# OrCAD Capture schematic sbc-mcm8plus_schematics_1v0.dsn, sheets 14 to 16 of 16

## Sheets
14 14. UARTs, uSD, FlexSPI, etc.: size A2; title: SBC-MCM8PLUS   14. UARTs, uSD, FlexSPI, etc.
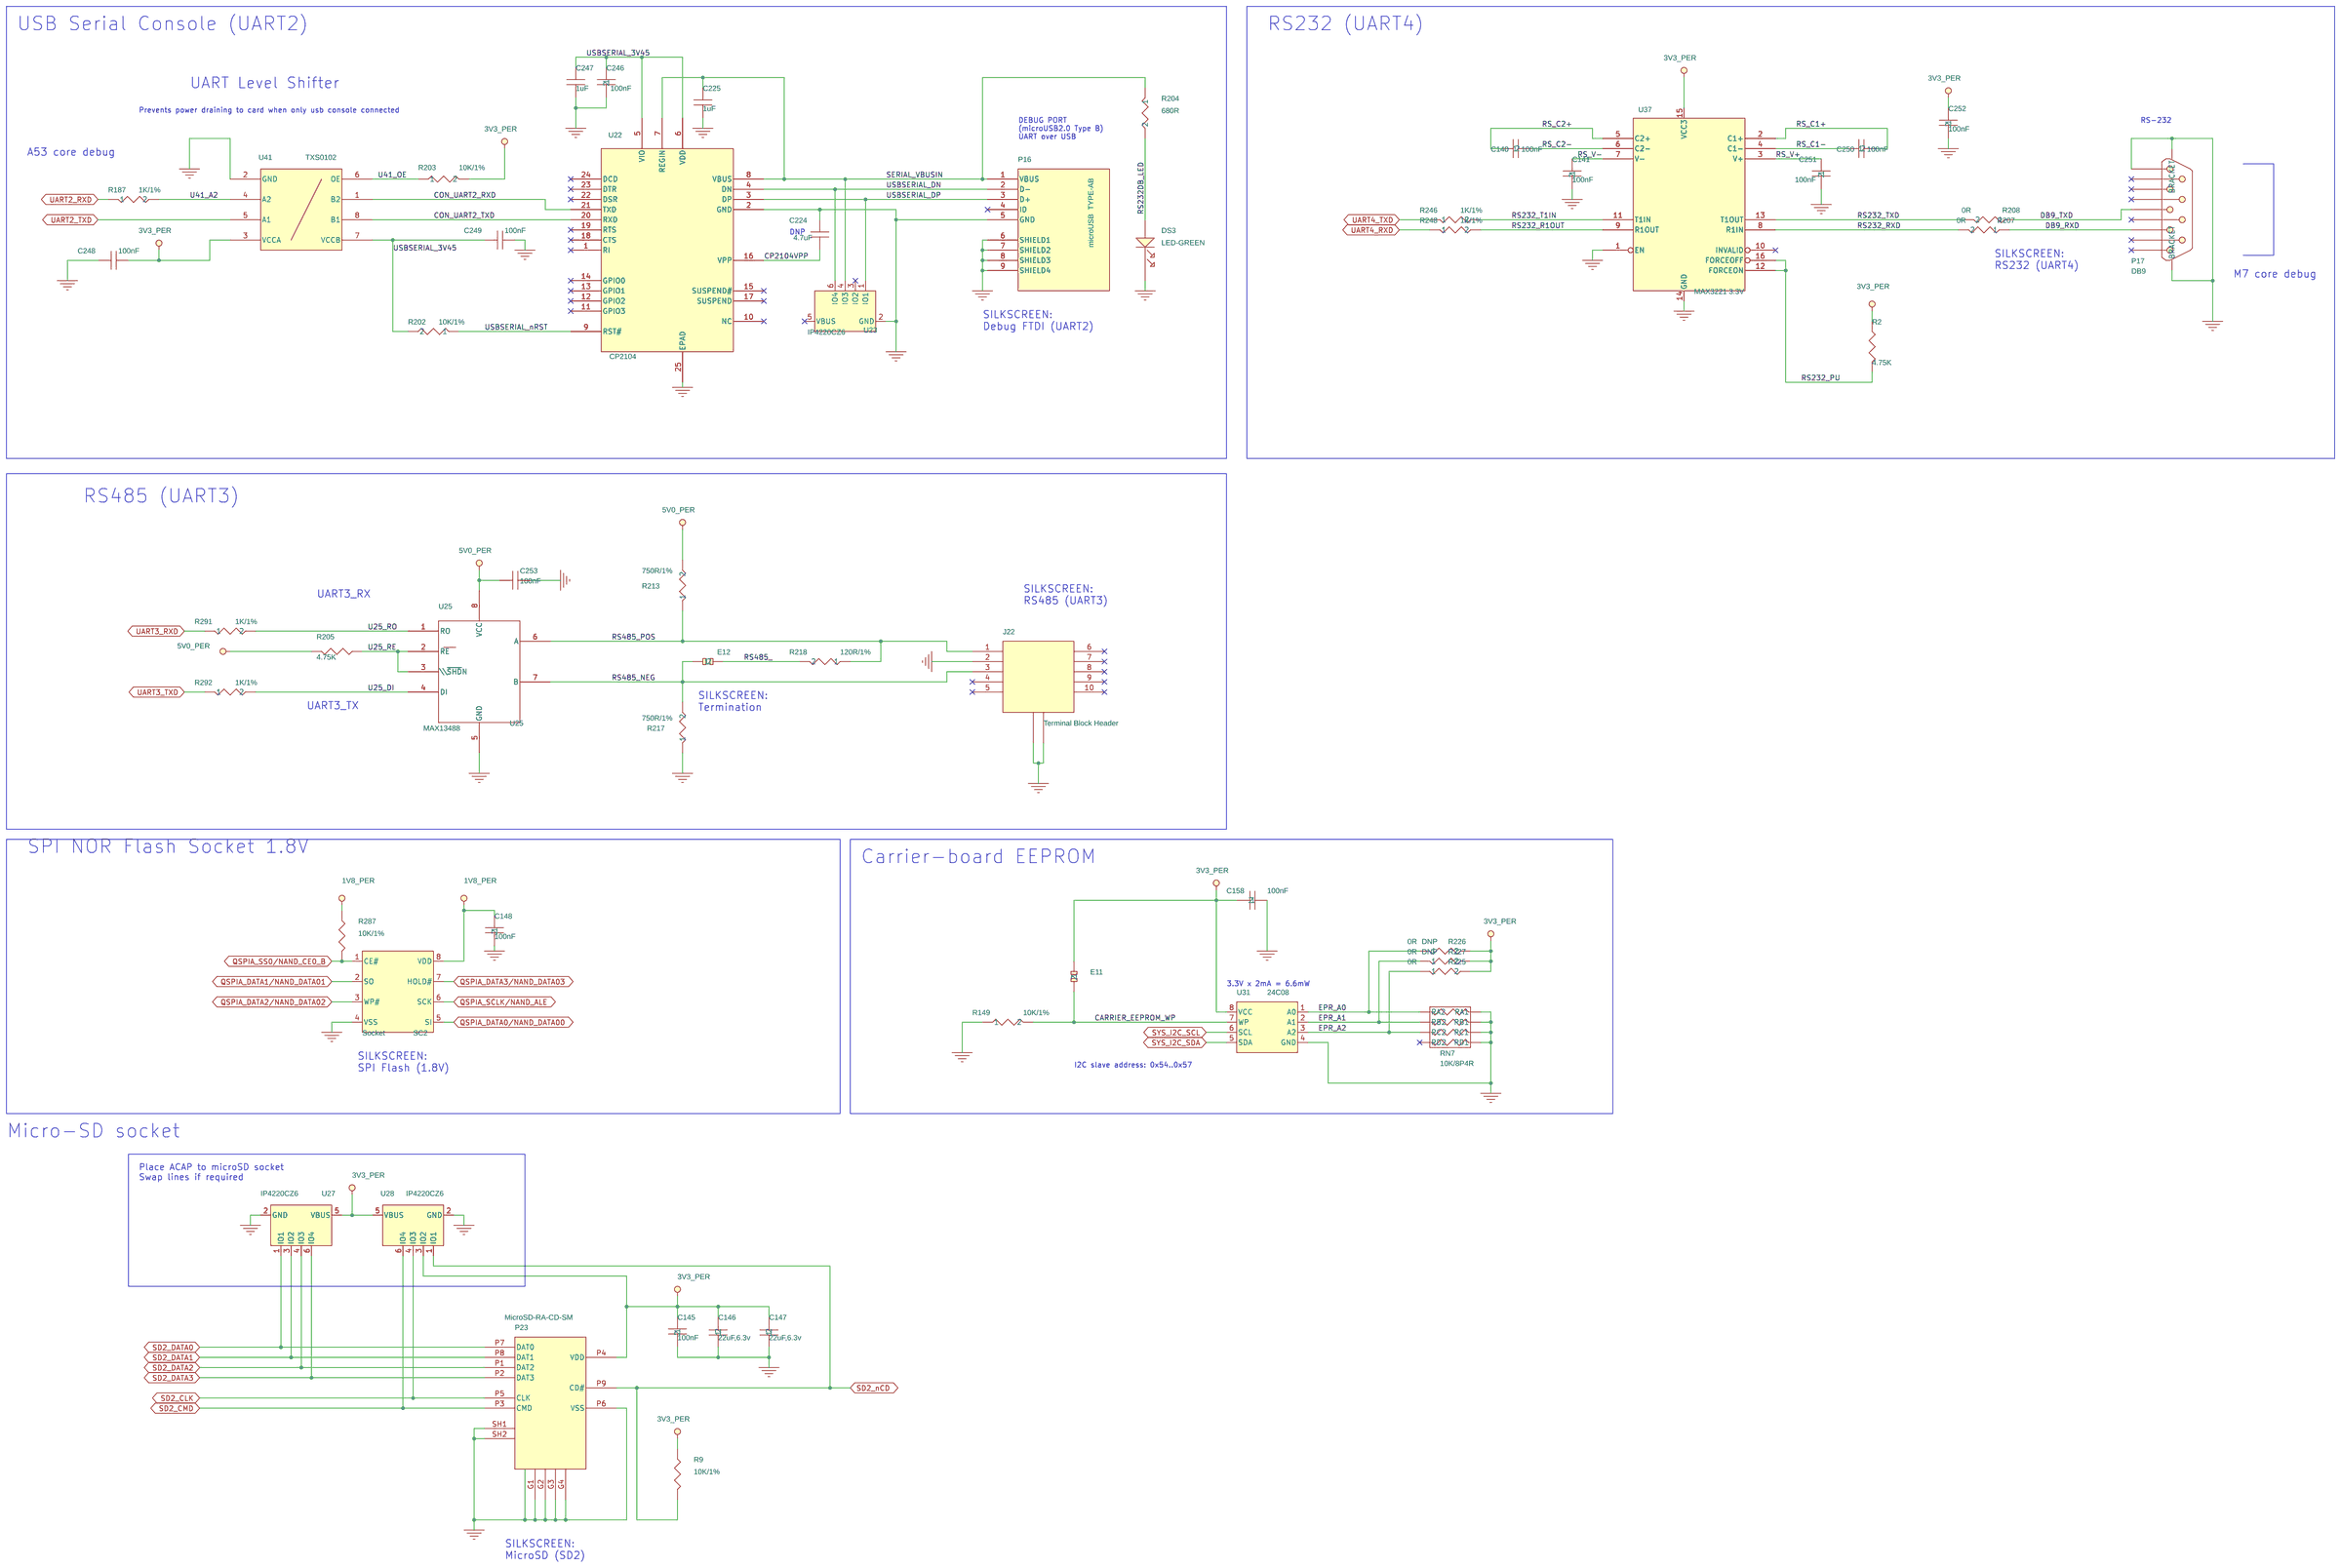
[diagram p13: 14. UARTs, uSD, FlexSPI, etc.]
15 15. WiFi + BT on SDHC1: size A3; title: SBC-MCM8PLUS   15. WiFi + BT on SDHC1
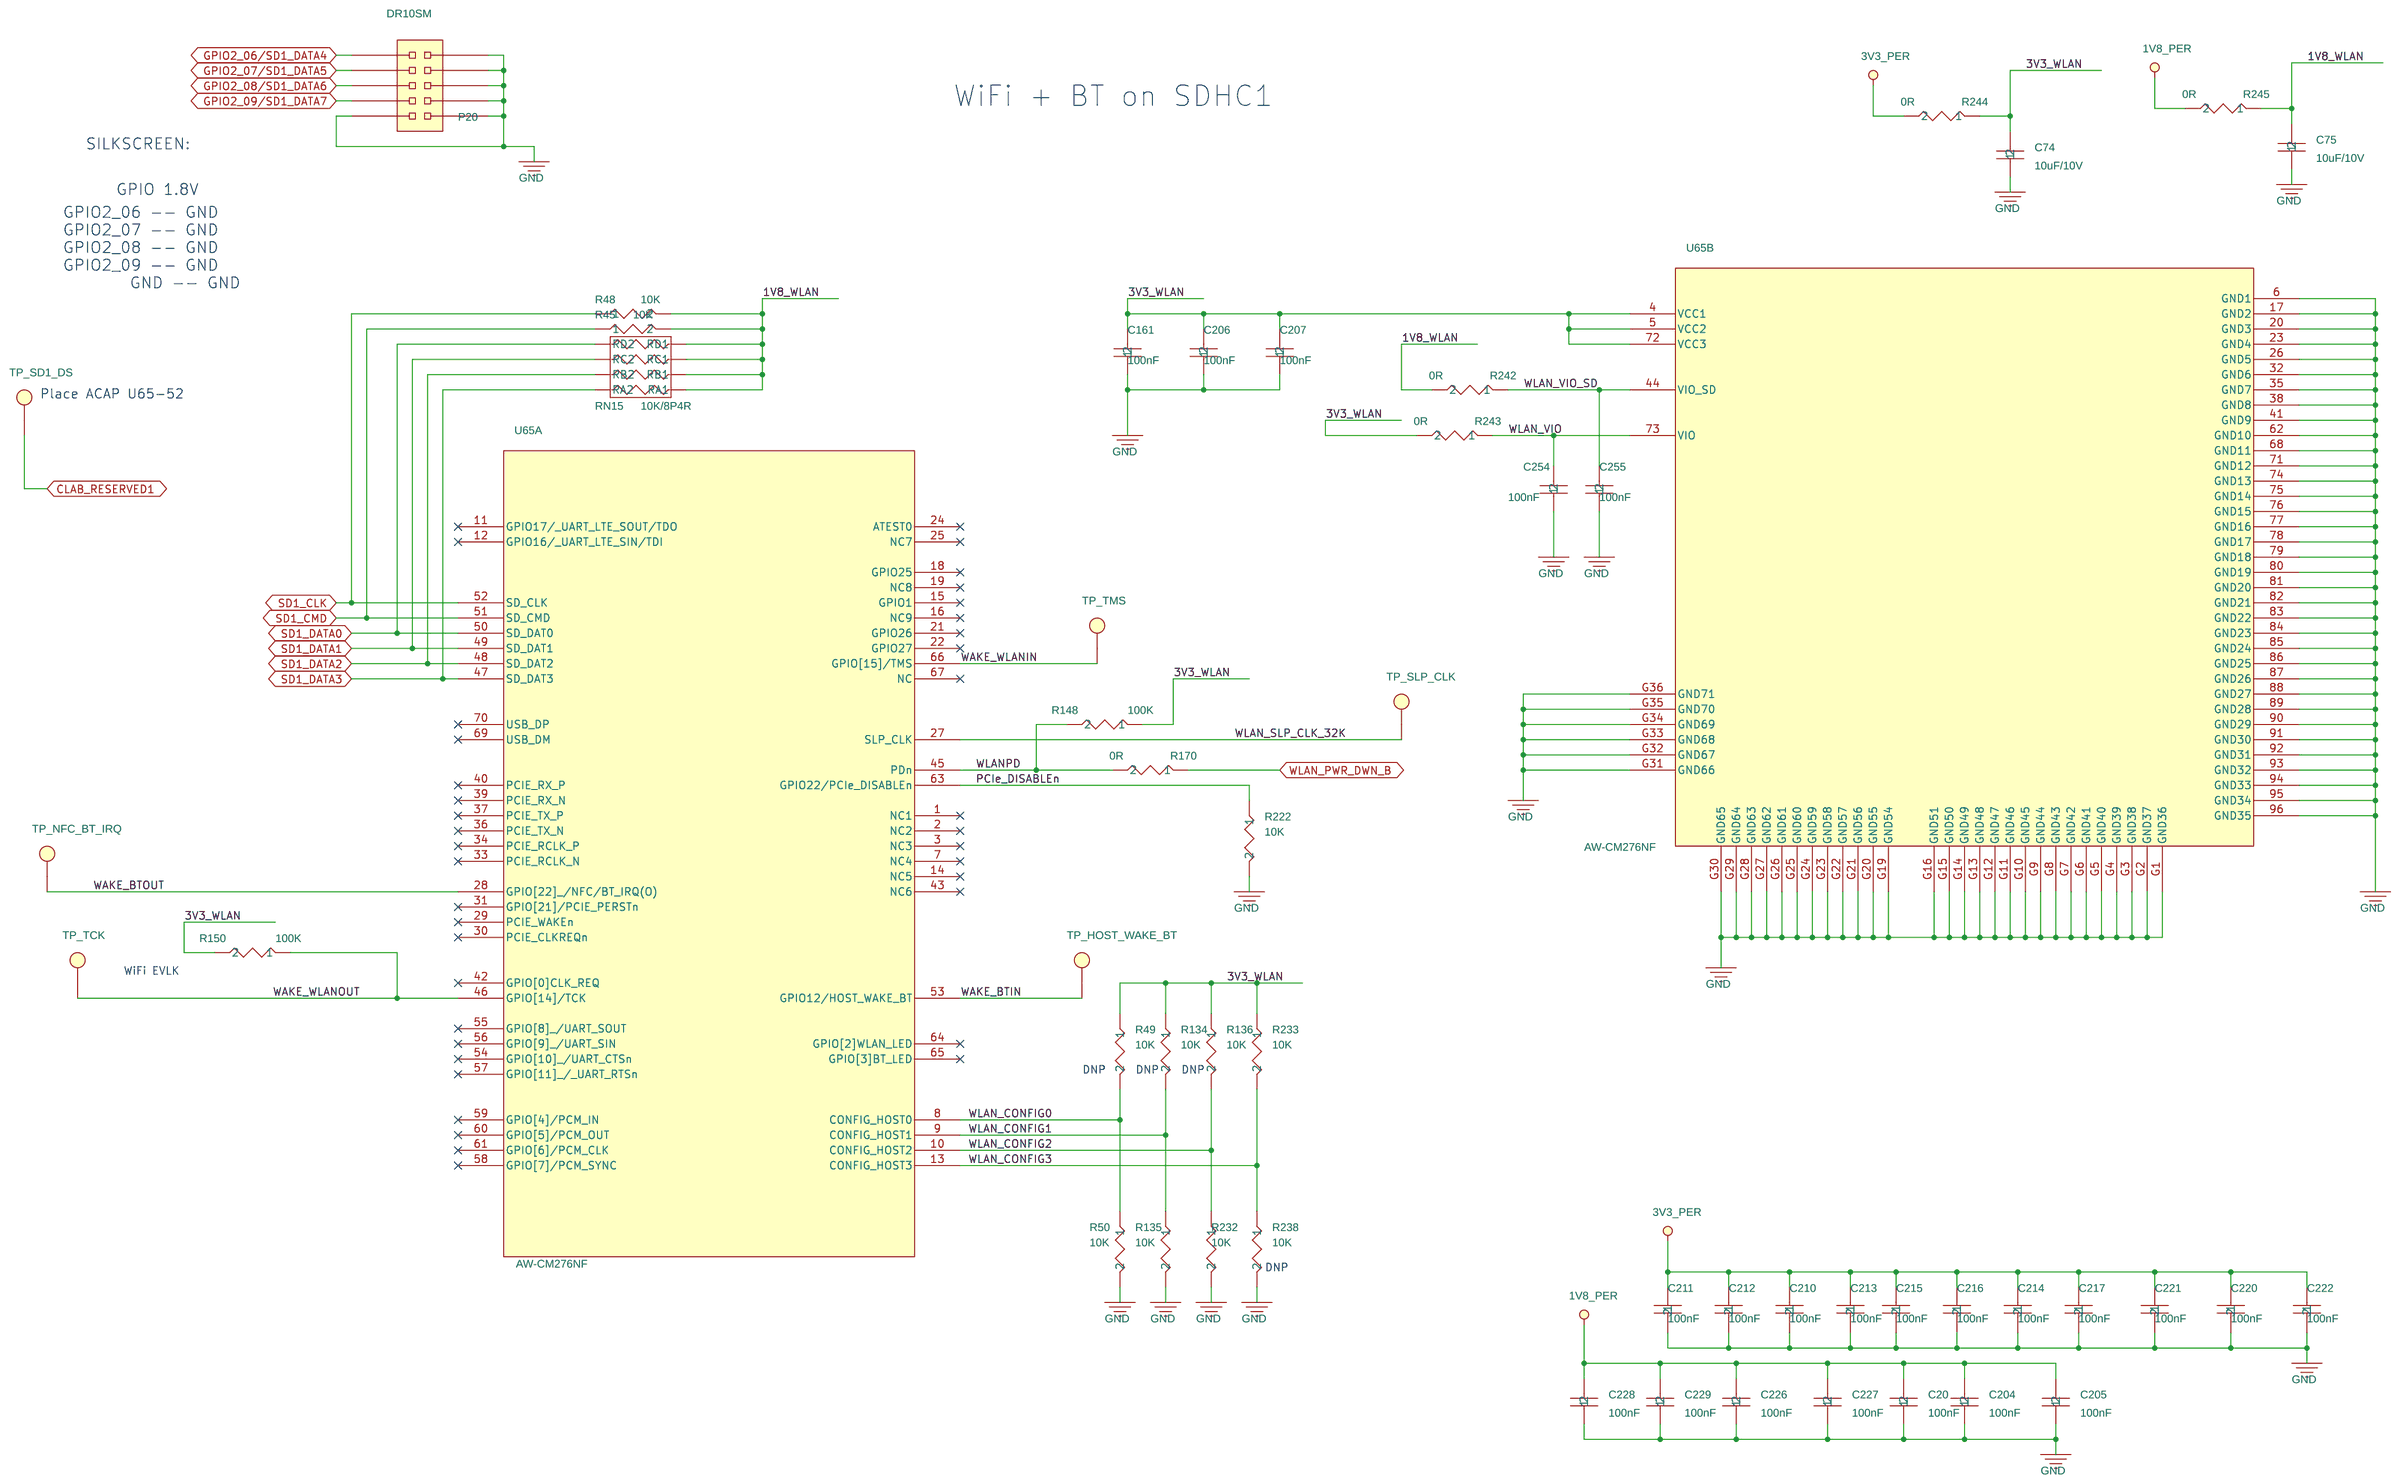
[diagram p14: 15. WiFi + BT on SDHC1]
16 05. USB1/2 (3.0), USB1 SDL Mode: size A3; title: SBC-MCM8PLUS   05. USB1/2 (3.0), USB1 SDL Mode
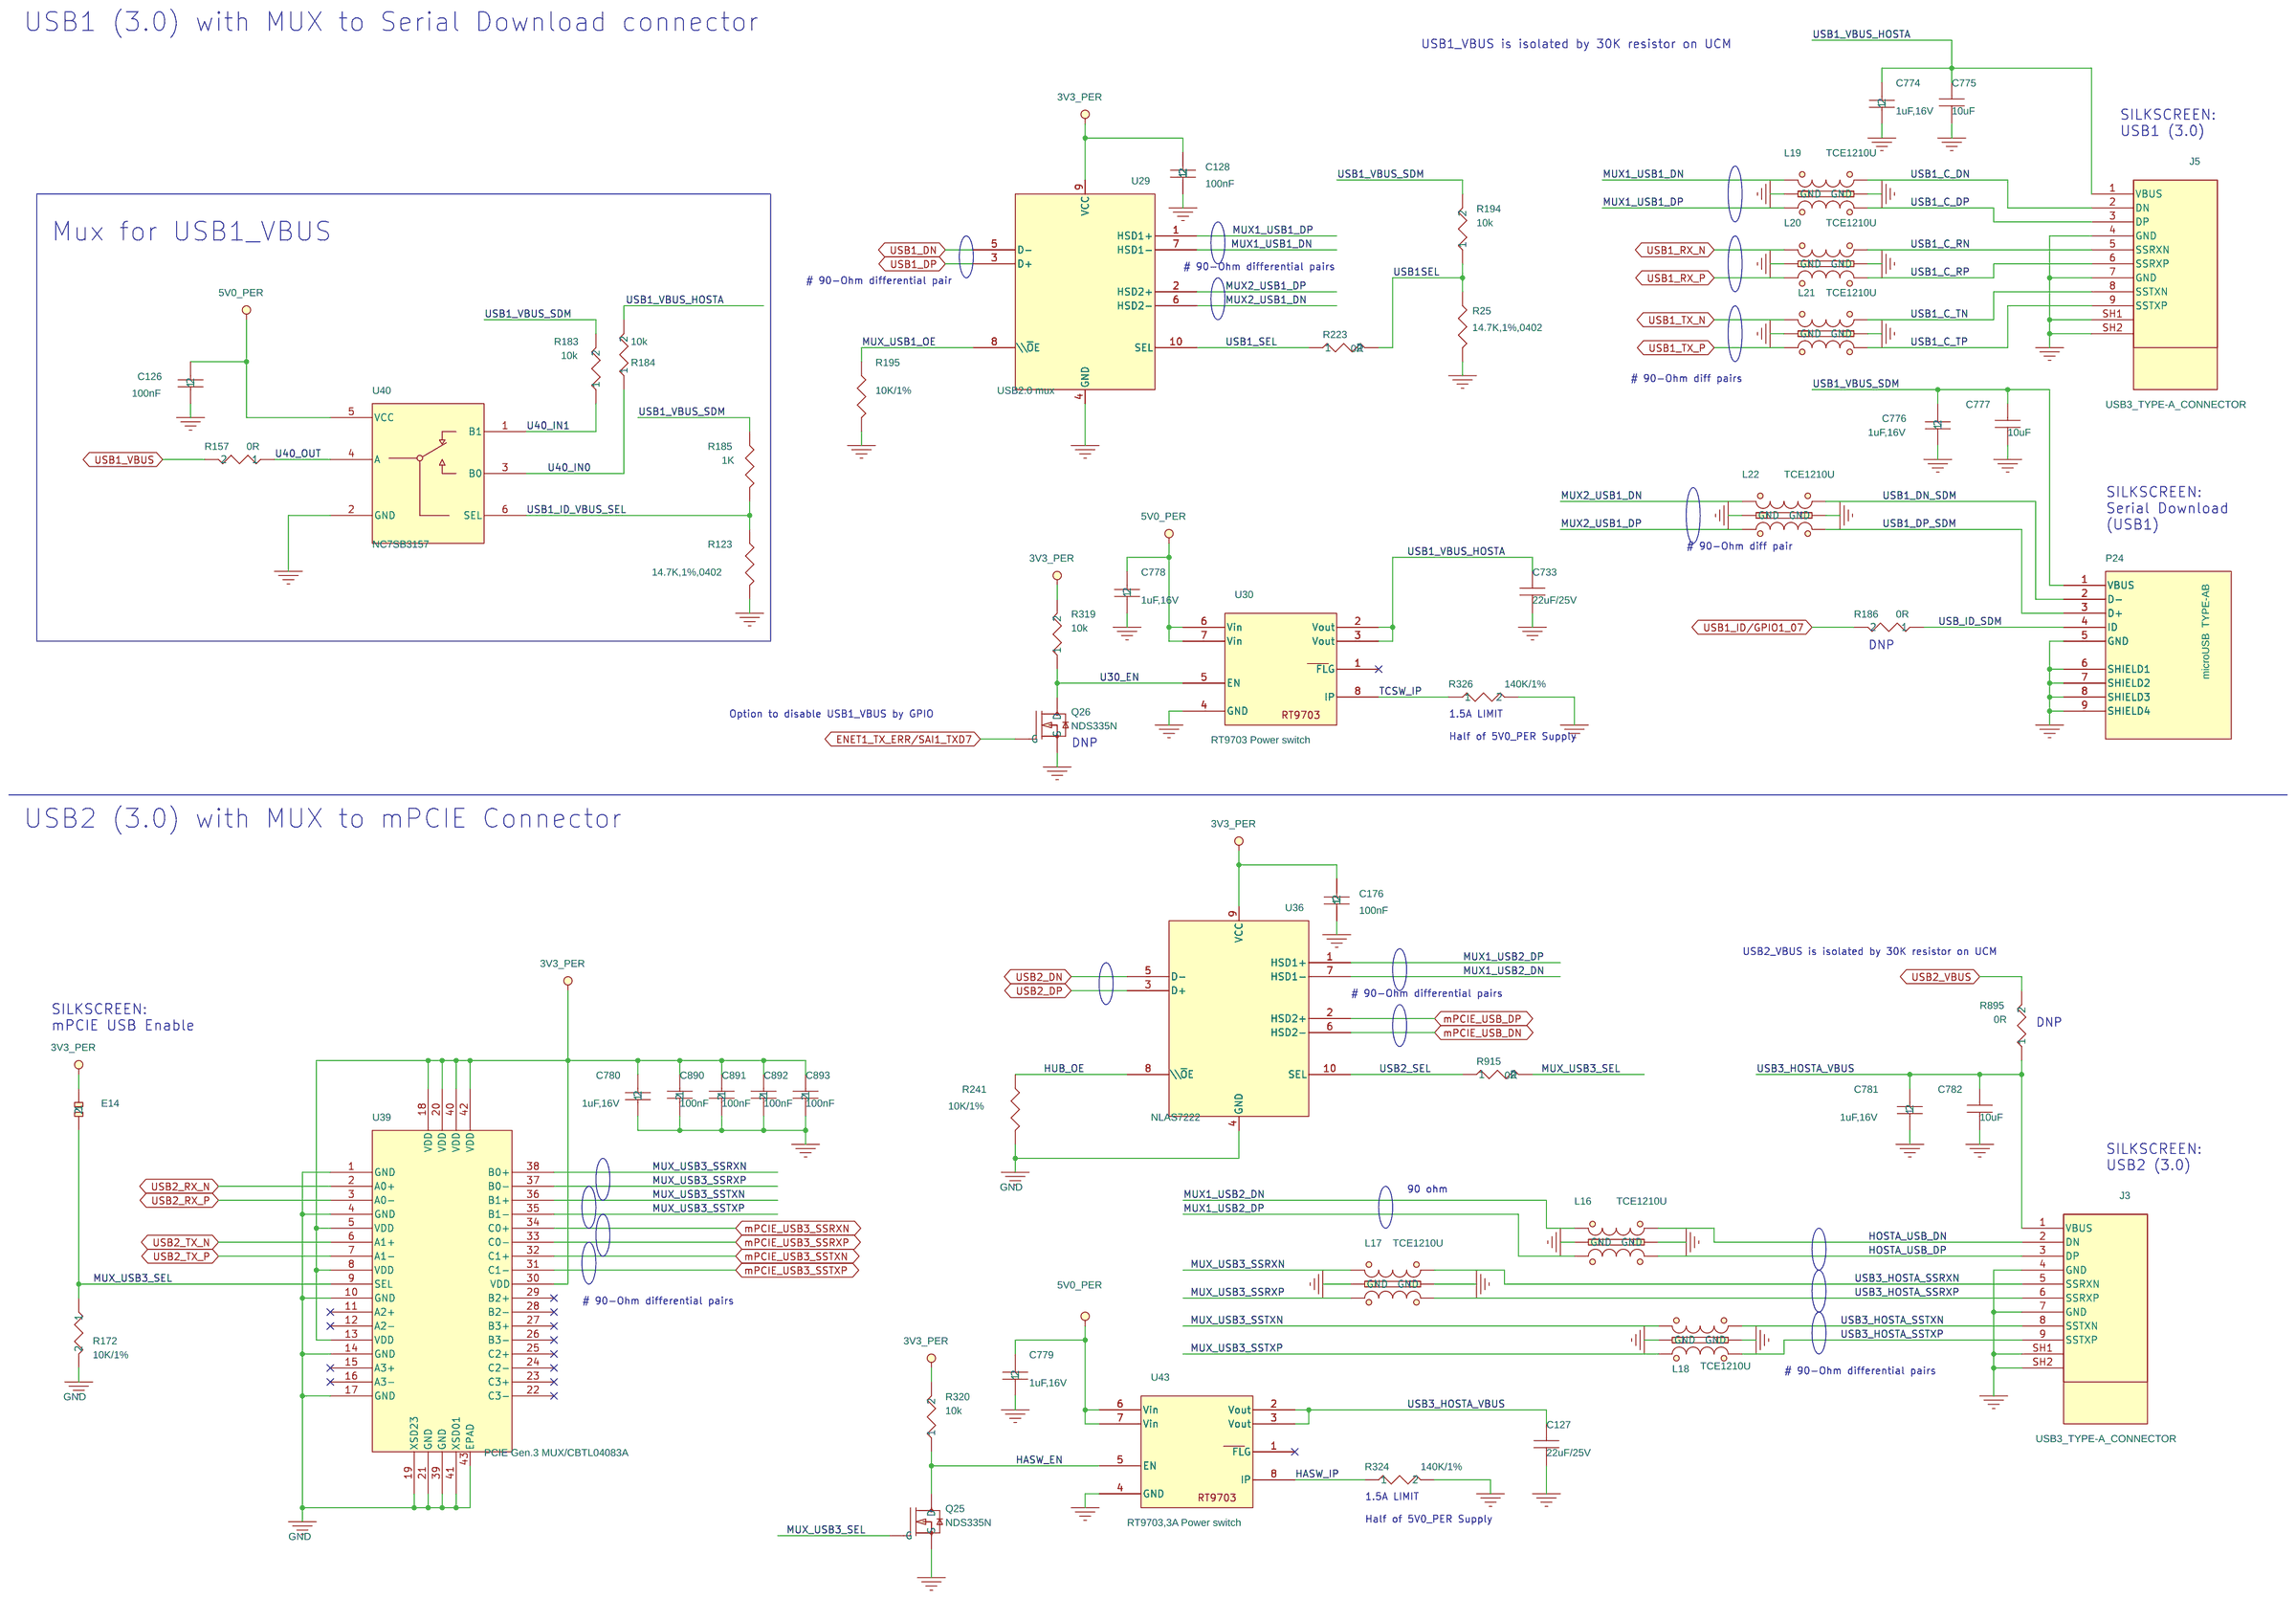
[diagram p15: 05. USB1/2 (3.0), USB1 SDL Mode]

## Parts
sheet 05. USB1/2 (3.0), USB1 SDL Mode
C126  100nF  [RC0402]
C127  22uF/25V  [C0805]
C128  100nF  [RC0402]
C176  100nF  [RC0402]
C733  22uF/25V  [C0805]
C774  1uF,16V  [RC0402]
C775  10uF  [C0603-08]
C776  1uF,16V  [RC0402]
C777  10uF  [C0603-08]
C778  1uF,16V  [RC0402]
C779  1uF,16V  [RC0402]
C780  1uF,16V  [RC0402]
C781  1uF,16V  [RC0402]
C782  10uF  [C0603-08]
C890  100nF  [RC0402]
C891  100nF  [RC0402]
C892  100nF  [RC0402]
C893  100nF  [RC0402]
E14  HDR1X2  [1X2THHDR]
J3  USB3_TYPE-A_CONNECTOR  [USB3_TYPEA]
J5  USB3_TYPE-A_CONNECTOR  [USB3_TYPEA]
L16  TCE1210U  [EMI1012-ESD]
L17  TCE1210U  [EMI1012-ESD]
L18  TCE1210U  [EMI1012-ESD]
L19  TCE1210U  [EMI1012-ESD]
L20  TCE1210U  [EMI1012-ESD]
L21  TCE1210U  [EMI1012-ESD]
L22  TCE1210U  [EMI1012-ESD]
P24  microUSB  TYPE-AB  [MICRO-USB-AB-RA-SM]
Q25  NDS335N  [SOT23]
Q26  NDS335N  [SOT23]
R25  14.7K,1%,0402  [RC0402]
R123  14.7K,1%,0402  [RC0402]
R157  0R  [RC0402]
R172  10K/1%  [RC0402]
R183  10k  [RC0402]
R184  10k  [RC0402]
R185  1K  [RC0402]
R186  0R  [RC0402]
R194  10k  [RC0402]
R195  10K/1%  [RC0402]
R223  0R  [RC0402]
R241  10K/1%  [RC0402]
R319  10k  [RC0402]
R320  10k  [RC0402]
R324  140K/1%  [RC0402]
R326  140K/1%  [RC0402]
R895  0R  [RC0402]
R915  0R  [RC0402]
U29  USB2.0 mux  [MO-255U1418E]
U30  RT9703 Power switch  [SO8-150]
U36  NLAS7222  [MO-255U1418E]
U39  PCIE Gen.3 MUX/CBTL04083A  [MO-220VMFD-2x7.5]
U40  NC7SB3157  [SC70-6]
U43  RT9703,3A Power switch  [SO8-150]
sheet 14. UARTs, uSD, FlexSPI, etc.
C140  100nF  [RC0402]
C141  100nF  [RC0402]
C145  100nF  [RC0402]
C146  22uF,6.3v  [RC0603]
C147  22uF,6.3v  [RC0603]
C148  100nF  [RC0402]
C158  100nF  [RC0402]
C224  4.7uF  [C0603-08]
C225  1uF  [RC0402]
C246  100nF  [RC0402]
C247  1uF  [RC0402]
C248  100nF  [RC0402]
C249  100nF  [RC0402]
C250  100nF  [RC0402]
C251  100nF  [RC0402]
C252  100nF  [RC0402]
C253  100nF  [RC0402]
DS3  LED-GREEN  [LED-1206]
E11  HDR1X2  [1X2THHDR]
E12  HDR1X2  [1X2THHDR]
J22  Terminal Block Header  [TB2.54mmRA-2x5P]
P16  microUSB  TYPE-AB  [MICRO-USB-AB-RA-SM]
P17  DB9  [DB9RATH]
P23  MicroSD-RA-CD-SM  [MicroSD-RA-CD-SM]
R2  4.75K  [RC0402]
R9  10K/1%  [RC0402]
R149  10K/1%  [RC0402]
R187  1K/1%  [RC0402]
R202  10K/1%  [RC0402]
R203  10K/1%  [RC0402]
R204  680R  [RC0402]
R205  4.75K  [RC0402]
R207  0R  [RC0402]
R208  0R  [RC0402]
R213  750R/1%  [RC0402]
R217  750R/1%  [RC0402]
R218  120R/1%  [RC0603]
R225  0R  [RC0402]
R226  0R  [RC0402]
R227  0R  [RC0402]
R246  1K/1%  [RC0402]
R248  1K/1%  [RC0402]
R287  10K/1%  [RC0402]
R291  1K/1%  [RC0402]
R292  1K/1%  [RC0402]
RN7  10K/8P4R  [RESNET8P0805]
SC2  Socket  [SKT-SOIC-8-200]
U22  CP2104  [MO-220VGGD-8]
U23  IP4220CZ6  [SOT23-6L-H1]
U25  MAX13488  [SO8-150]
U27  IP4220CZ6  [SOT23-6L]
U28  IP4220CZ6  [SOT23-6L]
U31  24C08  [MO-229VCED-2]
U37  MAX3221 3.3V  [SSOP-16]
U41  TXS0102  [MO-187DA-8]
sheet 15. WiFi + BT on SDHC1
C20  100nF  [RC0402]
C74  10uF/10V  [0402]
C75  10uF/10V  [0402]
C161  100nF  [RC0402]
C204  100nF  [RC0402]
C205  100nF  [RC0402]
C206  100nF  [RC0402]
C207  100nF  [RC0402]
C210  100nF  [RC0402]
C211  100nF  [RC0402]
C212  100nF  [RC0402]
C213  100nF  [RC0402]
C214  100nF  [RC0402]
C215  100nF  [RC0402]
C216  100nF  [RC0402]
C217  100nF  [RC0402]
C220  100nF  [RC0402]
C221  100nF  [RC0402]
C222  100nF  [RC0402]
C226  100nF  [RC0402]
C227  100nF  [RC0402]
C228  100nF  [RC0402]
C229  100nF  [RC0402]
C254  100nF  [RC0402]
C255  100nF  [RC0402]
P20  DR10SM  [2X5SMHDR]
R45  10K  [RC0402]
R48  10K  [RC0402]
R49  10K  [RC0402]
R50  10K  [RC0402]
R134  10K  [RC0402]
R135  10K  [RC0402]
R136  10K  [RC0402]
R148  100K  [RC0402]
R150  100K  [RC0402]
R170  0R  [RC0402]
R222  10K  [RC0402]
R232  10K  [RC0402]
R233  10K  [RC0402]
R238  10K  [RC0402]
R242  0R  [RC0402]
R243  0R  [RC0402]
R244  0R  [RC0402]
R245  0R  [RC0402]
RN15  10K/8P4R  [RESNET8P0805]
TP_HOST_WAKE_BT  TP  [TP_TH_0p5mm]
TP_NFC_BT_IRQ  TP  [TP_TH_0p5mm]
TP_SD1_DS  TP  [TP_TH_0p5mm]
TP_SLP_CLK  TP  [TP_TH_0p5mm]
TP_TCK  TP  [TP_TH_0p5mm]
TP_TMS  TP  [TP_TH_0p5mm]
U65  AW-CM276NF  [LGA-96-1216-AW]  (sections A,B)

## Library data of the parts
C126 = 100nF,_10V,_X7R,_10%,_0402_7: CLABCONF0: = SBC-MCM8PLUS; Group: LAN2
C127 = 22uF,25V,_0805: CLABCONF0: = SBC-MCM8PLUS
C128 = 100nF,_10V,_X7R,_10%,_0402_9: CLABCONF0: = SBC-MCM8PLUS; Group: LAN2
C176 = 100nF,_10V,_X7R,_10%,_0402_5: CLABCONF0: = SBC-MCM8PLUS; Group: LAN2
C733 = 22uF,25V,_0805_1: CLABCONF0: = SBC-MCM8PLUS
C774 = 100nF,_10V,_X7R,_10%,_0402: CLABCONF0: = SBC-MCM8PLUS; P/N: 151C10500S
C775 C777 C782 = 10uF,6_0.3V,0603,20%X5R: CLABCONF0: = SBC-MCM8PLUS
C776 = 100nF,_10V,_X7R,_10%,_0402_3: CLABCONF0: = SBC-MCM8PLUS; P/N: 151C10500S
C778 = 100nF,_10V,_X7R,_10%,_0402_6: CLABCONF0: = SBC-MCM8PLUS; P/N: 151C10500S
C779 = 100nF,_10V,_X7R,_10%,_0402_12: CLABCONF0: = SBC-MCM8PLUS; P/N: 151C10500S
C780 = 100nF,_10V,_X7R,_10%,_0402_11: CLABCONF0: = SBC-MCM8PLUS; P/N: 151C10500S
C781 = 100nF,_10V,_X7R,_10%,_0402_4: CLABCONF0: = SBC-MCM8PLUS; P/N: 151C10500S
C890 = 100nF,_10V,_X7R,_10%,_0402_8: CLABCONF0: = SBC-MCM8PLUS
C140 C891 = 100nF,_10V,_X7R,_10%,_0402_1: CLABCONF0: = SBC-MCM8PLUS
C148 C892 = 100nF,_10V,_X7R,_10%,_0402_10: CLABCONF0: = SBC-MCM8PLUS
C141 C893 = 100nF,_10V,_X7R,_10%,_0402_2: CLABCONF0: = SBC-MCM8PLUS
E12 E14 = HDR_1x2_100MIL_TH_JUMPER: CLABCONF0: = SBC-MCM8PLUS
J3 J5 = USB3_TYPEA_CONNECTER_0: CLABCONF0: = SBC-MCM8PLUS
L16-L22 = ESD_CHOKE_DIFFx2_10: CLABCONF0: = SBC-MCM8PLUS; P/N: 142D11801S
P16 P24 = Conn.,_Micro-USB,_B-Type: CLABCONF0: = SBC-MCM8PLUS; P/N: 180K00501S
Q25 = N-MOSFET,NDS335N,100mOhm@2.5V: CLABCONF0: = SBC-MCM8PLUS
Q26 = N-MOSFET,NDS335N,100mOhm@2.5V: CLABCONF0: DNP
R25 R123 = RESISTOR: CLABCONF0: = SBC-MCM8PLUS; P/N: 161C14721S
R157 = 0R,_0402_4: CLABCONF0: = SBC-MCM8PLUS
R172 R203 = 10K,1%,0402,1_16W: CLABCONF0: = SBC-MCM8PLUS
R135 R183 = 1M_,5%,_0402_4: CLABCONF0: = SBC-MCM8PLUS; P/N: 161C10021S
R48 R184 = 1M_,5%,_0402: CLABCONF0: = SBC-MCM8PLUS; P/N: 161C10021S
R185 = RESISTOR: CLABCONF0: = SBC-MCM8PLUS; P/N: 161C10011S
R186 = 0R,_0402_2: CLABCONF0: DNP
R194 = 1M_,5%,_0402_1: CLABCONF0: = SBC-MCM8PLUS; P/N: 161C10021S
R9 R195 = 10K,1%,0402,1_16W_0_1: CLABCONF0: = SBC-MCM8PLUS
R223 = 0R,_0402_3: CLABCONF0: = SBC-MCM8PLUS
R241 = 10K,1%,0402,1_16W_0: CLABCONF0: = SBC-MCM8PLUS
R50 R319 = 1M_,5%,_0402_2: CLABCONF0: = SBC-MCM8PLUS; P/N: 161C10021S
R320 = 1M_,5%,_0402_3: CLABCONF0: = SBC-MCM8PLUS; P/N: 161C10021S
R324 = 100K,_1%,_0402,_1_16W: CLABCONF0: = SBC-MCM8PLUS; P/N: 161C14031S
R326 = 100K,_1%,_0402,_1_16W_1: CLABCONF0: = SBC-MCM8PLUS; P/N: 161C14031S
R895 = 0R,_0402: CLABCONF0: DNP
R225 R915 = 0R,_0402_1: CLABCONF0: = SBC-MCM8PLUS
U29 U36 = USB2_0.0_mux: CLABCONF0: = SBC-MCM8PLUS; P/N: 116A72220S
U30 U43 = RT9703,3A_Power_switch+FLG: CLABCONF0: = SBC-MCM8PLUS
U39 = PCIE_Mux_Demux_2_1_2: CLABCONF0: = SBC-MCM8PLUS; P/N: 116A24123S
U40 = Bus_switch_2_1: CLABCONF0: = SBC-MCM8PLUS
C145 = 100nF,_10V,_X7R,_10%,_0402_7: CLABCONF0: = SBC-MCM8PLUS
C146 = 100nF,_10V,_X7R,_10%,_0402_8: CLABCONF0: = SBC-MCM8PLUS; P/N: 151B22610S
C147 = 100nF,_10V,_X7R,_10%,_0402_9: CLABCONF0: = SBC-MCM8PLUS; P/N: 151B22610S
C158 = 100nF,_10V,_X7R,_10%,_0402_4: CLABCONF0: = SBC-MCM8PLUS
C224 = 4.7uF,_6.3V,_X5R,_20%,_0603: CLABCONF0: DNP; P/N: 151B10610S
C225 C247 = 1uF,X5R,6.3V,0402: CLABCONF0: = SBC-MCM8PLUS
C246 = 100nF,_10V,_X7R,_10%,_0402: CLABCONF0: = SBC-MCM8PLUS
C248 C249 C253 = 100nF,_10V,_X7R,_10%,_0402_0: CLABCONF0: = SBC-MCM8PLUS
C250 = 100nF,_10V,_X7R,_10%,_0402_3: CLABCONF0: = SBC-MCM8PLUS
C251 = 100nF,_10V,_X7R,_10%,_0402_5: CLABCONF0: = SBC-MCM8PLUS
C252 = 100nF,_10V,_X7R,_10%,_0402_6: CLABCONF0: = SBC-MCM8PLUS
DS3 = LED-GREEN_1206_2: CLABCONF0: = SBC-MCM8PLUS
E11 = HDR_1x2_100MIL_TH_JUMPER_1: CLABCONF0: = SBC-MCM8PLUS
J22 = Terminal_Block_Header_2x5P_2.54: CLABCONF0: = SBC-MCM8PLUS
P17 = DB9_RA_TH_Male_ATX: CLABCONF0: = SBC-MCM8PLUS
P23 = microSD_push-pull: CLABCONF0: = SBC-MCM8PLUS; P/N: 182K01300S
R2 = 10K,1%,0402,1_16W_0_3: CLABCONF0: = SBC-MCM8PLUS; Group: Always; P/N: 161C47511S
R149 = 10K,1%,0402,1_16W_1: CLABCONF0: = SBC-MCM8PLUS
R187 = 1K,1%,0402,1_16W_1: CLABCONF0: = SBC-MCM8PLUS; Group: CAN
R202 = 10K,1%,0402,1_16W_4: CLABCONF0: = SBC-MCM8PLUS
R204 = 47K,_0402: CLABCONF0: = SBC-MCM8PLUS; P/N: 161C68001S
R205 = 10K,1%,0402,1_16W_0: CLABCONF0: = SBC-MCM8PLUS; Group: Always; P/N: 161C47511S
R207 = 0R,_0402_1_2: CLABCONF0: = SBC-MCM8PLUS
R208 = 0R,_0402_1_4: CLABCONF0: = SBC-MCM8PLUS
R213 = 10K,1%,0402,1_16W_2: CLABCONF0: = SBC-MCM8PLUS; P/N: 161C75001S
R217 = 10K,1%,0402,1_16W_3: CLABCONF0: = SBC-MCM8PLUS; P/N: 161C75001S
R218 = 120R_1%,_0603: CLABCONF0: = SBC-MCM8PLUS
R226 = 0R,_0402_1_1: CLABCONF0: DNP
R227 = 0R,_0402_1_3: CLABCONF0: DNP
R246 = 1K,1%,0402,1_16W_4: CLABCONF0: = SBC-MCM8PLUS; Group: CAN
R248 = 1K,1%,0402,1_16W: CLABCONF0: = SBC-MCM8PLUS; Group: CAN
R287 = 10K,1%,0402,1_16W_0_2: CLABCONF0: = SBC-MCM8PLUS
R291 = 1K,1%,0402,1_16W_2: CLABCONF0: = SBC-MCM8PLUS; Group: CAN
R292 = 1K,1%,0402,1_16W_3: CLABCONF0: = SBC-MCM8PLUS; Group: CAN
RN7 RN15 = RN,10K,8P4R@0805: CLABCONF0: = SBC-MCM8PLUS
SC2 = IC,SPI_FLASH,16_Mbit_0: CLABCONF0: = SBC-MCM8PLUS; P/N: 190A00800S
U22 = CP2104_2: CLABCONF0: = SBC-MCM8PLUS; P/N: 116A00140S
U23 U27 U28 = IP4220CZ6_0: CLABCONF0: = SBC-MCM8PLUS
U25 = SN65HVD72D_0: CLABCONF0: = SBC-MCM8PLUS; P/N: 116A00430S
U31 = 24C02,_serial_EE,_2KB,_I2C: CLABCONF0: = SBC-MCM8PLUS; P/N: 111S31000S
U37 = MAX3221_RS-232_1T1R_3_2.3V_XCVR: CLABCONF0: = SBC-MCM8PLUS
U41 = TXS0102_0: CLABCONF0: = SBC-MCM8PLUS; P/N: 116A01020S
C20 = 100nF,_10V,_X7R,_10%,_0402_9: CLABCONF0: = SBC-MCM8PLUS; P/N: 151B10400S
C74 = 10uF_10V_20%_0402: CLABCONF0: = SBC-MCM8PLUS
C75 = 10uF_10V_20%_0402_1: CLABCONF0: = SBC-MCM8PLUS
C161 = 100nF,_10V,_X7R,_10%,_0402_8: CLABCONF0: = SBC-MCM8PLUS; P/N: 151B10400S
C204 = 100nF,_10V,_X7R,_10%,_0402_18: CLABCONF0: = SBC-MCM8PLUS; P/N: 151B10400S
C205 = 100nF,_10V,_X7R,_10%,_0402_2: CLABCONF0: = SBC-MCM8PLUS; P/N: 151B10400S
C206 = 100nF,_10V,_X7R,_10%,_0402_19: CLABCONF0: = SBC-MCM8PLUS; P/N: 151B10400S
C207 = 100nF,_10V,_X7R,_10%,_0402_7: CLABCONF0: = SBC-MCM8PLUS; P/N: 151B10400S
C210 = 100nF,_10V,_X7R,_10%,_0402_11: CLABCONF0: = SBC-MCM8PLUS; P/N: 151B10400S
C211 = 100nF,_10V,_X7R,_10%,_0402: CLABCONF0: = SBC-MCM8PLUS; P/N: 151B10400S
C212 = 100nF,_10V,_X7R,_10%,_0402_10: CLABCONF0: = SBC-MCM8PLUS; P/N: 151B10400S
C213 = 100nF,_10V,_X7R,_10%,_0402_22: CLABCONF0: = SBC-MCM8PLUS; P/N: 151B10400S
C214 = 100nF,_10V,_X7R,_10%,_0402_15: CLABCONF0: = SBC-MCM8PLUS; P/N: 151B10400S
C215 = 100nF,_10V,_X7R,_10%,_0402_5: CLABCONF0: = SBC-MCM8PLUS; P/N: 151B10400S
C216 = 100nF,_10V,_X7R,_10%,_0402_13: CLABCONF0: = SBC-MCM8PLUS; P/N: 151B10400S
C217 = 100nF,_10V,_X7R,_10%,_0402_1: CLABCONF0: = SBC-MCM8PLUS; P/N: 151B10400S
C220 = 100nF,_10V,_X7R,_10%,_0402_21: CLABCONF0: = SBC-MCM8PLUS; P/N: 151B10400S
C221 = 100nF,_10V,_X7R,_10%,_0402_12: CLABCONF0: = SBC-MCM8PLUS; P/N: 151B10400S
C222 = 100nF,_10V,_X7R,_10%,_0402_20: CLABCONF0: = SBC-MCM8PLUS; P/N: 151B10400S
C226 = 100nF,_10V,_X7R,_10%,_0402_17: CLABCONF0: = SBC-MCM8PLUS; P/N: 151B10400S
C227 = 100nF,_10V,_X7R,_10%,_0402_4: CLABCONF0: = SBC-MCM8PLUS; P/N: 151B10400S
C228 = 100nF,_10V,_X7R,_10%,_0402_6: CLABCONF0: = SBC-MCM8PLUS; P/N: 151B10400S
C229 = 100nF,_10V,_X7R,_10%,_0402_14: CLABCONF0: = SBC-MCM8PLUS; P/N: 151B10400S
C254 = 100nF,_10V,_X7R,_10%,_0402_16: CLABCONF0: = SBC-MCM8PLUS; P/N: 151B10400S
C255 = 100nF,_10V,_X7R,_10%,_0402_3: CLABCONF0: = SBC-MCM8PLUS; P/N: 151B10400S
P20 = HDR_2x5_100MIL_SMT: CLABCONF0: = SBC-MCM8PLUS; P/N: 190C01000S
R45 = 1M_,5%,_0402_5: CLABCONF0: = SBC-MCM8PLUS; P/N: 161C10021S
R49 = 1M_,5%,_0402_7: CLABCONF0: DNP; P/N: 161C10021S
R134 = 1M_,5%,_0402_3: CLABCONF0: DNP; P/N: 161C10021S
R136 = 1M_,5%,_0402_8: CLABCONF0: DNP; P/N: 161C10021S
R148 = 100K,_0402_1: CLABCONF0: = SBC-MCM8PLUS; P/N: 161C10031S
R150 = 100K,_0402: CLABCONF0: = SBC-MCM8PLUS; P/N: 161C10031S
R170 = 0R,_0402_0: CLABCONF0: = SBC-MCM8PLUS; P/N: 161C00005S
R222 = 1M_,5%,_0402_10: CLABCONF0: = SBC-MCM8PLUS; P/N: 161C10021S
R232 = 1M_,5%,_0402_9: CLABCONF0: = SBC-MCM8PLUS; P/N: 161C10021S
R233 = 1M_,5%,_0402_6: CLABCONF0: = SBC-MCM8PLUS; P/N: 161C10021S
R238 = 1M_,5%,_0402_1: CLABCONF0: DNP; P/N: 161C10021S
R242 = 0R,_0402_0_2: CLABCONF0: = SBC-MCM8PLUS; P/N: 161C00005S
R243 = 0R,_0402_0_1: CLABCONF0: = SBC-MCM8PLUS; P/N: 161C00005S
R244 = 0R,_0402_0_4: CLABCONF0: = SBC-MCM8PLUS; P/N: 161C00005S
R245 = 0R,_0402_0_3: CLABCONF0: = SBC-MCM8PLUS; P/N: 161C00005S
TP_HOST_WAKE_BT TP_NFC_BT_IRQ TP_SD1_DS TP_SLP_CLK TP_TCK TP_TMS = TP_SMT_0: CLABCONF0: DNP
U65 = AW-CM276NF: CLABCONF0: = SBC-MCM8PLUS; P/N: 116B00550S; Color: Default; Location X-Coordinate: 0; Location Y-Coordinate: 0; Power Pins Visible: False; Primitive: DEFAULT

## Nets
1V8_PER: C20.2 C148.1 C204.2 C205.2 C226.2 C227.2 C228.2 C229.2 R245.2 R287.1 SC2.8(VDD) ; also on sheet 4 5 9 10 12 13
1V8_WLAN: C75.2 R45.2 R48.2 R242.2 R245.1 RN15.1(RA1) RN15.2(RB1) RN15.3(RC1) RN15.4(RD1)
3V3_PER: C128.2 C145.1 C146.2 C147.2 C158.2 C176.2 C210.1 C211.1 C212.1 C213.1 C214.1 C215.1 C216.1 C217.1 C220.1 C221.1 C222.1 C248.1 C252.1 C780.2 C890.1 C891.1 C892.1 C893.1 E11.1 E14.1 P23.P4(VDD) R2.1 R9.1 R203.2 R225.2 R226.2 R227.2 R244.2 R319.2 R320.2 U27.5(VBUS) U28.3(IO2) U28.5(VBUS) U29.9(VCC) U31.8(VCC) U36.9(VCC) U37.15(VCC3) U39.5(VDD) U39.8(VDD) U39.13(VDD) U39.18(VDD) U39.20(VDD) U39.30(VDD) U39.40(VDD) U39.42(VDD) U41.3(VCCA) ; also on sheet 2 3 4 5 6 7 9 10 11 12 13
3V3_WLAN: C74.2 C161.2 C206.2 C207.2 R49.1 R134.1 R136.1 R148.1 R150.2 R233.1 R243.2 R244.1 U65.4(VCC1) U65.5(VCC2) U65.72(VCC3)
5V0_PER: C126.2 C253.2 C778.2 C779.2 R205.2 R213.2 U25.8(VCC) U30.6(Vin) U30.7(Vin) U40.5(VCC) U43.6(Vin) U43.7(Vin) ; also on sheet 6 7 9 10 13
GND: C20.1 C74.1 C75.1 C126.1 C127.2 C128.1 C141.2 C145.2 C146.1 C147.1 C148.2 C158.1 C161.1 C176.1 C204.1 C205.1 C206.1 C207.1 C210.2 C211.2 C212.2 C213.2 C214.2 C215.2 C216.2 C217.2 C220.2 C221.2 C222.2 C224.2 C225.2 C226.1 C227.1 C228.1 C229.1 C246.2 C247.2 C248.2 C249.1 C251.2 C252.2 C253.1 C254.1 C255.1 C733.2 C774.1 C775.2 C776.1 C777.2 C778.1 C779.1 C780.1 C781.1 C782.2 C890.2 C891.2 C892.2 C893.2 DS3.CATHODE J3.4(GND) J3.7(GND) J3.SH1 J3.SH2 J5.4(GND) J5.7(GND) J5.SH1 J5.SH2 J22.2(2A) J22.CHASSIS L16.5(GND) L16.6(GND) L17.5(GND) L17.6(GND) L18.5(GND) L18.6(GND) L19.5(GND) L19.6(GND) L20.5(GND) L20.6(GND) L21.5(GND) L21.6(GND) L22.5(GND) L22.6(GND) P16.5(GND) P16.6(SHIELD1) P16.7(SHIELD2) P16.8(SHIELD3) P16.9(SHIELD4) P17.5 P17.10(BRACKET) P17.11(BRACKET) P20.2 P20.4 P20.6 P20.8 P20.9 P20.10 P23.G1 P23.G2 P23.G3 P23.G4 P23.P6(VSS) P23.SH1 P23.SH2 P24.5(GND) P24.6(SHIELD1) P24.7(SHIELD2) P24.8(SHIELD3) P24.9(SHIELD4) Q25.2(S) Q26.2(S) R25.2 R50.2 R123.2 R135.2 R149.1 R172.2 R195.1 R217.1 R222.2 R232.2 R238.2 R241.1 R324.2 R326.2 RN7.1(RA1) RN7.2(RB1) RN7.3(RC1) RN7.4(RD1) SC2.4(VSS) U22.2(GND) U22.25(EPAD) U23.2(GND) U25.5(GND) U27.2(GND) U28.2(GND) U29.4(GND) U30.4(GND) U31.4(GND) U36.4(GND) U37.1(EN) U37.14(GND) U39.1(GND) U39.4(GND) U39.10(GND) U39.14(GND) U39.17(GND) U39.19(XSD23) U39.21(GND) U39.39(GND) U39.41(XSD01) U39.43(EPAD) U40.2(GND) U41.2(GND) U43.4(GND) U65.6(GND1) U65.17(GND2) U65.20(GND3) U65.23(GND4) U65.26(GND5) U65.32(GND6) U65.35(GND7) U65.38(GND8) U65.41(GND9) U65.62(GND10) U65.68(GND11) U65.71(GND12) U65.74(GND13) U65.75(GND14) U65.76(GND15) U65.77(GND16) U65.78(GND17) U65.79(GND18) U65.80(GND19) U65.81(GND20) U65.82(GND21) U65.83(GND22) U65.84(GND23) U65.85(GND24) U65.86(GND25) U65.87(GND26) U65.88(GND27) U65.89(GND28) U65.90(GND29) U65.91(GND30) U65.92(GND31) U65.93(GND32) U65.94(GND33) U65.95(GND34) U65.96(GND35) U65.G1(GND36) U65.G2(GND37) U65.G3(GND38) U65.G4(GND39) U65.G5(GND40) U65.G6(GND41) U65.G7(GND42) U65.G8(GND43) U65.G9(GND44) U65.G10(GND45) U65.G11(GND46) U65.G12(GND47) U65.G13(GND48) U65.G14(GND49) U65.G15(GND50) U65.G16(GND51) U65.G19(GND54) U65.G20(GND55) U65.G21(GND56) U65.G22(GND57) U65.G23(GND58) U65.G24(GND59) U65.G25(GND60) U65.G26(GND61) U65.G27(GND62) U65.G28(GND63) U65.G29(GND64) U65.G30(GND65) U65.G31(GND66) U65.G32(GND67) U65.G33(GND68) U65.G34(GND69) U65.G35(GND70) U65.G36(GND71) ; also on sheet 1 2 3 4 5 6 7 9 10 11 12 13
CARRIER_EEPROM_WP: E11.2 R149.2 U31.7(WP)
CLAB_RESERVED1: TP_SD1_DS.1 ; also on sheet 3
CON_UART2_RXD: U22.21(TXD) U41.1(B2)
CON_UART2_TXD: U22.20(RXD) U41.8(B1)
CP2104VPP: C224.1 U22.16(VPP)
DB9_RXD: P17.2 R207.1
DB9_TXD: P17.3 R208.1
ENET1_TX_ERR/SAI1_TXD7: Q26.1(G) ; also on sheet 2 10
EPR_A0: R226.1 RN7.8(RA2) U31.1(A0)
EPR_A1: R227.1 RN7.7(RB2) U31.2(A1)
EPR_A2: R225.1 RN7.6(RC2) U31.3(A2)
GPIO2_06/SD1_DATA4: P20.1 ; also on sheet 3
GPIO2_07/SD1_DATA5: P20.3 ; also on sheet 3
GPIO2_08/SD1_DATA6: P20.5 ; also on sheet 3
GPIO2_09/SD1_DATA7: P20.7 ; also on sheet 3
HASW_EN: Q25.3(D) R320.1 U43.5(EN)
HASW_IP: R324.1 U43.8(IP)
HOSTA_USB_DN: J3.2(DN) L16.4
HOSTA_USB_DP: J3.3(DP) L16.3
HUB_OE: R241.2 U36.8(\\~{O}E)
mPCIE_USB3_SSRXN: U39.34(C0+) ; also on sheet 12
mPCIE_USB3_SSRXP: U39.33(C0-) ; also on sheet 12
mPCIE_USB3_SSTXN: U39.32(C1+) ; also on sheet 12
mPCIE_USB3_SSTXP: U39.31(C1-) ; also on sheet 12
mPCIE_USB_DN: U36.6(HSD2-) ; also on sheet 12
mPCIE_USB_DP: U36.2(HSD2+) ; also on sheet 12
MUX1_USB1_DN: L19.2 U29.7(HSD1-)
MUX1_USB1_DP: L19.1 U29.1(HSD1+)
MUX1_USB2_DN: L16.1 U36.7(HSD1-)
MUX1_USB2_DP: L16.2 U36.1(HSD1+)
MUX2_USB1_DN: L22.2 U29.6(HSD2-)
MUX2_USB1_DP: L22.1 U29.2(HSD2+)
MUX_USB1_OE: R195.2 U29.8(\\~{O}E)
MUX_USB3_SEL: E14.2 Q25.1(G) R172.1 R915.2 U39.9(SEL)
MUX_USB3_SSRXN: L17.2 U39.38(B0+)
MUX_USB3_SSRXP: L17.1 U39.37(B0-)
MUX_USB3_SSTXN: L18.2 U39.36(B1+)
MUX_USB3_SSTXP: L18.1 U39.35(B1-)
PCIe_DISABLEn: R222.1 U65.63(GPIO22/PCIe_DISABLEn)
QSPIA_DATA0/NAND_DATA00: SC2.5(SI) ; also on sheet 2
QSPIA_DATA1/NAND_DATA01: SC2.2(SO) ; also on sheet 2
QSPIA_DATA2/NAND_DATA02: SC2.3(WP#) ; also on sheet 2
QSPIA_DATA3/NAND_DATA03: SC2.7(HOLD#) ; also on sheet 2
QSPIA_SCLK/NAND_ALE: SC2.6(SCK) ; also on sheet 2
QSPIA_SS0/NAND_CE0_B: R287.2 SC2.1(CE#) ; also on sheet 2
RS232_PU: R2.2 U37.12(FORCEON) U37.16(FORCEOFF)
RS232_R1OUT: R248.2 U37.9(R1OUT)
RS232_RXD: R207.2 U37.8(R1IN)
RS232_T1IN: R246.2 U37.11(T1IN)
RS232_TXD: R208.2 U37.13(T1OUT)
RS232DB_LED: DS3.ANODE R204.2
RS485_: E12.2 R218.2
RS485_NEG: E12.1 J22.3(3A) R217.2 U25.7(B)
RS485_POS: J22.1(1A) R213.1 R218.1 U25.6(A)
RS_C1+: C250.2 U37.2(C1+)
RS_C1-: C250.1 U37.4(C1-)
RS_C2+: C140.1 U37.5(C2+)
RS_C2-: C140.2 U37.6(C2-)
RS_V+: C251.1 U37.3(V+)
RS_V-: C141.1 U37.7(V-)
SD1_CLK: R48.1 U65.52(SD_CLK) ; also on sheet 3
SD1_CMD: R45.1 U65.51(SD_CMD) ; also on sheet 3
SD1_DATA0: RN15.5(RD2) U65.50(SD_DAT0) ; also on sheet 3
SD1_DATA1: RN15.6(RC2) U65.49(SD_DAT1) ; also on sheet 3
SD1_DATA2: RN15.7(RB2) U65.48(SD_DAT2) ; also on sheet 3
SD1_DATA3: RN15.8(RA2) U65.47(SD_DAT3) ; also on sheet 3
SD2_CLK: P23.P5(CLK) U28.4(IO3) ; also on sheet 3
SD2_CMD: P23.P3(CMD) U28.6(IO4) ; also on sheet 3
SD2_DATA0: P23.P7(DAT0) U27.1(IO1) ; also on sheet 3
SD2_DATA1: P23.P8(DAT1) U27.3(IO2) ; also on sheet 3
SD2_DATA2: P23.P1(DAT2) U27.4(IO3) ; also on sheet 3
SD2_DATA3: P23.P2(DAT3) U27.6(IO4) ; also on sheet 3
SD2_nCD: P23.P9(CD#) R9.2 U28.1(IO1) ; also on sheet 3
SERIAL_VBUSIN: C225.1 P16.1(VBUS) R204.1 U22.7(REGIN) U22.8(VBUS) U23.4(IO3)
SYS_I2C_SCL: U31.6(SCL) ; also on sheet 3 10 12
SYS_I2C_SDA: U31.5(SDA) ; also on sheet 3 10 12
TCSW_IP: R326.1 U30.8(IP)
U25_DI: R292.2 U25.4(DI)
U25_RE: R205.1 U25.2(RE) U25.3(\\~{SHD}N)
U25_RO: R291.2 U25.1(RO)
U30_EN: Q26.3(D) R319.1 U30.5(EN)
U40_IN0: R184.1 U40.3(B0)
U40_IN1: R183.1 U40.1(B1)
U40_OUT: R157.1 U40.4(A)
U41_A2: R187.2 U41.4(A2)
U41_OE: R203.1 U41.6(OE)
UART2_RXD: R187.1 ; also on sheet 3 10
UART2_TXD: U41.5(A1) ; also on sheet 3 10
UART3_RXD: R291.1 ; also on sheet 2 10
UART3_TXD: R292.1 ; also on sheet 2 10
UART4_RXD: R248.1 ; also on sheet 3 10
UART4_TXD: R246.1 ; also on sheet 3 10
USB1_C_DN: J5.2(DN) L19.3
USB1_C_DP: J5.3(DP) L19.4
USB1_C_RN: J5.5(SSRXN) L20.4
USB1_C_RP: J5.6(SSRXP) L20.3
USB1_C_TN: J5.8(SSTXN) L21.3
USB1_C_TP: J5.9(SSTXP) L21.4
USB1_DN: U29.5(D-) ; also on sheet 3
USB1_DN_SDM: L22.3 P24.2(D-)
USB1_DP: U29.3(D+) ; also on sheet 3
USB1_DP_SDM: L22.4 P24.3(D+)
USB1_ID/GPIO1_07: R186.2 ; also on sheet 2 10
USB1_ID_VBUS_SEL: R123.1 R185.2 U40.6(SEL)
USB1_RX_N: L20.1 ; also on sheet 3
USB1_RX_P: L20.2 ; also on sheet 3
USB1_SEL: R223.1 U29.10(SEL)
USB1_TX_N: L21.2 ; also on sheet 2
USB1_TX_P: L21.1 ; also on sheet 2
USB1_VBUS: R157.2 ; also on sheet 3
USB1_VBUS_HOSTA: C733.1 C774.2 C775.1 J5.1(VBUS) R184.2 U30.2(Vout) U30.3(Vout)
USB1_VBUS_SDM: C776.2 C777.1 P24.1(VBUS) R183.2 R185.1 R194.2
USB1SEL: R25.1 R194.1 R223.2
USB2_DN: U36.5(D-) ; also on sheet 3
USB2_DP: U36.3(D+) ; also on sheet 3
USB2_RX_N: U39.2(A0+) ; also on sheet 3
USB2_RX_P: U39.3(A0-) ; also on sheet 3
USB2_SEL: R915.1 U36.10(SEL)
USB2_TX_N: U39.6(A1+) ; also on sheet 3
USB2_TX_P: U39.7(A1-) ; also on sheet 3
USB2_VBUS: R895.2 ; also on sheet 3
USB3_HOSTA_SSRXN: J3.5(SSRXN) L17.3
USB3_HOSTA_SSRXP: J3.6(SSRXP) L17.4
USB3_HOSTA_SSTXN: J3.8(SSTXN) L18.3
USB3_HOSTA_SSTXP: J3.9(SSTXP) L18.4
USB3_HOSTA_VBUS: C127.1 C781.2 C782.1 J3.1(VBUS) R895.1 U43.2(Vout) U43.3(Vout)
USB_ID_SDM: P24.4(ID) R186.1
USBSERIAL_3V45: C246.1 C247.1 C249.2 R202.2 U22.5(VIO) U22.6(VDD) U41.7(VCCB)
USBSERIAL_DN: P16.2(D-) U22.4(DN) U23.6(IO4)
USBSERIAL_DP: P16.3(D+) U22.3(DP) U23.1(IO1)
USBSERIAL_nRST: R202.1 U22.9(RST#)
WAKE_BTIN: TP_HOST_WAKE_BT.1 U65.53(GPIO12/HOST_WAKE_BT)
WAKE_BTOUT: TP_NFC_BT_IRQ.1 U65.28(GPIO[22]_/NFC/BT_IRQ(O))
WAKE_WLANIN: TP_TMS.1 U65.66(GPIO[15]/TMS)
WAKE_WLANOUT: R150.1 TP_TCK.1 U65.46(GPIO[14]/TCK)
WLAN_CONFIG0: R49.2 R50.1 U65.8(CONFIG_HOST0)
WLAN_CONFIG1: R134.2 R135.1 U65.9(CONFIG_HOST1)
WLAN_CONFIG2: R136.2 R232.1 U65.10(CONFIG_HOST2)
WLAN_CONFIG3: R233.2 R238.1 U65.13(CONFIG_HOST3)
WLAN_PWR_DWN_B: R170.1 ; also on sheet 10
WLAN_SLP_CLK_32K: TP_SLP_CLK.1 U65.27(SLP_CLK)
WLAN_VIO: C254.2 R243.1 U65.73(VIO)
WLAN_VIO_SD: C255.2 R242.1 U65.44(VIO_SD)
WLANPD: R148.2 R170.2 U65.45(PDn)

Not connected (* = marked no-connect by the designer): J22 4(4A)* 5(5A)* 6(6B)* 7(7B)* 8(8B)* 9(9B)* 10(10B)*; P16 4(ID)*; P17 1* 4* 6* 7* 8* 9*; RN7 5(RD2)*; U22 1(RI)* 10(NC)* 11(GPIO3)* 12(GPIO2)* 13(GPIO1)* 14(GPIO0)* 15(SUSPEND#)* 17(SUSPEND)* 18(CTS)* 19(RTS)* 22(DSR)* 23(DTR)* 24(DCD)*; U23 3(IO2)* 5(VBUS)*; U30 1(FLG)*; U37 10(INVALID)*; U39 11(A2+)* 12(A2-)* 15(A3+)* 16(A3-)* 22(C3-)* 23(C3+)* 24(C2-)* 25(C2+)* 26(B3-)* 27(B3+)* 28(B2-)* 29(B2+)*; U43 1(FLG)*; U65 1(NC1)* 2(NC2)* 3(NC3)* 7(NC4)* 11(GPIO17/_UART_LTE_SOUT/TDO)* 12(GPIO16/_UART_LTE_SIN/TDI)* 14(NC5)* 15(GPIO1)* 16(NC9)* 18(GPIO25)* 19(NC8)* 21(GPIO26)* 22(GPIO27)* 24(ATEST0)* 25(NC7)* 29(PCIE_WAKEn)* 30(PCIE_CLKREQn)* 31(GPIO[21]/PCIE_PERSTn)* 33(PCIE_RCLK_N)* 34(PCIE_RCLK_P)* 36(PCIE_TX_N)* 37(PCIE_TX_P)* 39(PCIE_RX_N)* 40(PCIE_RX_P)* 42(GPIO[0]CLK_REQ)* 43(NC6)* 54(GPIO[10]_/UART_CTSn)* 55(GPIO[8]_/UART_SOUT)* 56(GPIO[9]_/UART_SIN)* 57(GPIO[11]_/_UART_RTSn)* 58(GPIO[7]/PCM_SYNC)* 59(GPIO[4]/PCM_IN)* 60(GPIO[5]/PCM_OUT)* 61(GPIO[6]/PCM_CLK)* 64(GPIO[2]WLAN_LED)* 65(GPIO[3]BT_LED)* 67(NC)* 69(USB_DM)* 70(USB_DP)*

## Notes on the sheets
sheet 14
- USB Serial Console (UART2)
- RS232 (UART4)
- UART Level Shifter
- Prevents power draining to card when only usb console connected
- DEBUG PORT
  (microUSB2.0 Type B)
  UART over USB
- RS-232
- A53 core debug
- DNP
- SILKSCREEN:
  RS232 (UART4)
- M7 core debug
- SILKSCREEN:
  Debug FTDI (UART2)
- RS485 (UART3)
- SILKSCREEN:
  RS485 (UART3)
- UART3_RX
- SILKSCREEN:
  Termination
- UART3_TX
- SPI NOR Flash Socket 1.8V
- Carrier-board EEPROM
- 3.3V x 2mA = 6.6mW
- SILKSCREEN:
  SPI Flash (1.8V)
- I2C slave address: 0x54..0x57
- Micro-SD socket
- Place ACAP to microSD socket
  Swap lines if required
- SILKSCREEN:
  MicroSD (SD2)
sheet 15
- WiFi + BT on SDHC1
- SILKSCREEN:
- GPIO 1.8V
- GPIO2_06 -- GND
  GPIO2_07 -- GND
  GPIO2_08 -- GND
  GPIO2_09 -- GND
          GND -- GND
- Place ACAP U65-52
- WiFi EVLK
- DNP
- DNP
- DNP
- DNP
sheet 16
- USB1 (3.0) with MUX to Serial Download connector
- USB1_VBUS is isolated by 30K resistor on UCM
- SILKSCREEN:
  USB1 (3.0)
- Mux for USB1_VBUS
- # 90-Ohm differential pairs
- # 90-Ohm differential pair
- # 90-Ohm diff pairs
- SILKSCREEN:
  Serial Download
  (USB1)
- # 90-Ohm diff pair
- DNP
- Option to disable USB1_VBUS by GPIO
- 1.5A LIMIT
  Half of 5V0_PER Supply
- DNP
- USB2 (3.0) with MUX to mPCIE Connector
- USB2_VBUS is isolated by 30K resistor on UCM
- # 90-Ohm differential pairs
- SILKSCREEN:
  mPCIE USB Enable
- DNP
- SILKSCREEN:
  USB2 (3.0)
- 90 ohm
- # 90-Ohm differential pairs
- # 90-Ohm differential pairs
- 1.5A LIMIT
  Half of 5V0_PER Supply
